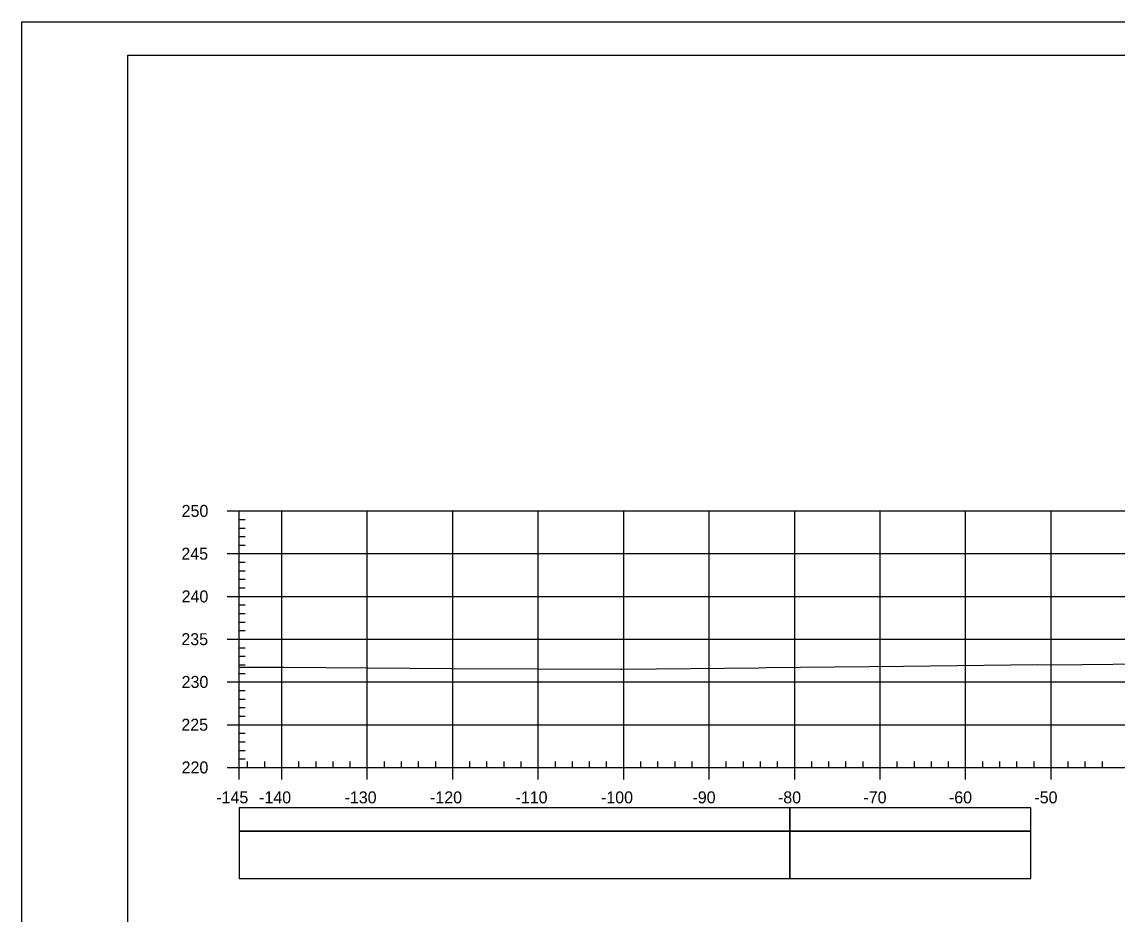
# Model space of a CAD drawing. Extents: x 1386544 to 1388153, y 379785 to 390999.
# Drawn here: x 1387819.8 to 1387948, y 384146.7 to 384251 of the extents above; entities that cross this region are included whole.
import ezdxf

# ---------------------------------------------------------------- set-up
doc = ezdxf.new("R2010")
doc.units = 0
for name, color, linetype in [('R_Axis', 7, 'Continuous'), ('R_Axis Annot', 7, 'Continuous'), ('R_Border', 7, 'Continuous'), ('R_Exist Surface', 7, 'Continuous'), ('R_Grid', 7, 'Continuous'), ('R_No Plot', 7, 'Continuous'), ('R_Striping', 7, 'Continuous')]:
    doc.layers.add(name, color=color, linetype=linetype)

msp = doc.modelspace()

# ---------------------------------------------------------------- linework, layer by layer
at = {"layer": 'R_Axis'}
for p, q in [((1387843.85, 384193.84), (1387845.25, 384193.84)), ((1387845.25, 384163.84), (1387845.25, 384193.84)), ((1387845.25, 384192.84), (1387845.95, 384192.84)), ((1387845.25, 384191.84), (1387845.95, 384191.84)), ((1387845.25, 384190.84), (1387845.95, 384190.84)), ((1387845.25, 384189.84), (1387845.95, 384189.84)), ((1387843.85, 384188.84), (1387845.25, 384188.84)), ((1387845.25, 384187.84), (1387845.95, 384187.84)), ((1387845.25, 384186.84), (1387845.95, 384186.84)), ((1387845.25, 384185.84), (1387845.95, 384185.84)), ((1387845.25, 384184.84), (1387845.95, 384184.84)), ((1387843.85, 384183.84), (1387845.25, 384183.84)), ((1387845.25, 384182.84), (1387845.95, 384182.84)), ((1387845.25, 384181.84), (1387845.95, 384181.84)), ((1387845.25, 384180.84), (1387845.95, 384180.84)), ((1387845.25, 384179.84), (1387845.95, 384179.84)), ((1387843.85, 384178.84), (1387845.25, 384178.84)), ((1387845.25, 384177.84), (1387845.95, 384177.84)), ((1387845.25, 384176.84), (1387845.95, 384176.84)), ((1387845.25, 384175.84), (1387845.95, 384175.84)), ((1387845.25, 384174.84), (1387845.95, 384174.84)), ((1387843.85, 384173.84), (1387845.25, 384173.84)), ((1387845.25, 384172.84), (1387845.95, 384172.84)), ((1387845.25, 384171.84), (1387845.95, 384171.84)), ((1387845.25, 384170.84), (1387845.95, 384170.84)), ((1387845.25, 384169.84), (1387845.95, 384169.84)), ((1387843.85, 384168.84), (1387845.25, 384168.84)), ((1387845.25, 384167.84), (1387845.95, 384167.84)), ((1387845.25, 384166.84), (1387845.95, 384166.84)), ((1387845.25, 384165.84), (1387845.95, 384165.84)), ((1387843.85, 384163.84), (1387845.25, 384163.84)), ((1387845.25, 384164.84), (1387845.95, 384164.84)), ((1387845.25, 384163.84), (1387845.25, 384164.54)), ((1387845.25, 384163.84), (1388135.25, 384163.84)), ((1387845.25, 384162.44), (1387845.25, 384163.84)), ((1387846.25, 384163.84), (1387846.25, 384164.54)), ((1387848.25, 384163.84), (1387848.25, 384164.54)), ((1387850.25, 384162.44), (1387850.25, 384163.84)), ((1387852.25, 384163.84), (1387852.25, 384164.54)), ((1387854.25, 384163.84), (1387854.25, 384164.54)), ((1387856.25, 384163.84), (1387856.25, 384164.54)), ((1387858.25, 384163.84), (1387858.25, 384164.54)), ((1387860.25, 384162.44), (1387860.25, 384163.84)), ((1387862.25, 384163.84), (1387862.25, 384164.54)), ((1387864.25, 384163.84), (1387864.25, 384164.54)), ((1387866.25, 384163.84), (1387866.25, 384164.54)), ((1387868.25, 384163.84), (1387868.25, 384164.54)), ((1387870.25, 384162.44), (1387870.25, 384163.84)), ((1387872.25, 384163.84), (1387872.25, 384164.54)), ((1387874.25, 384163.84), (1387874.25, 384164.54)), ((1387876.25, 384163.84), (1387876.25, 384164.54)), ((1387878.25, 384163.84), (1387878.25, 384164.54)), ((1387880.25, 384162.44), (1387880.25, 384163.84)), ((1387882.25, 384163.84), (1387882.25, 384164.54)), ((1387884.25, 384163.84), (1387884.25, 384164.54)), ((1387886.25, 384163.84), (1387886.25, 384164.54)), ((1387888.25, 384163.84), (1387888.25, 384164.54)), ((1387890.25, 384162.44), (1387890.25, 384163.84)), ((1387892.25, 384163.84), (1387892.25, 384164.54)), ((1387894.25, 384163.84), (1387894.25, 384164.54)), ((1387896.25, 384163.84), (1387896.25, 384164.54)), ((1387898.25, 384163.84), (1387898.25, 384164.54)), ((1387900.25, 384162.44), (1387900.25, 384163.84)), ((1387902.25, 384163.84), (1387902.25, 384164.54)), ((1387904.25, 384163.84), (1387904.25, 384164.54)), ((1387906.25, 384163.84), (1387906.25, 384164.54)), ((1387908.25, 384163.84), (1387908.25, 384164.54)), ((1387910.25, 384162.44), (1387910.25, 384163.84)), ((1387912.25, 384163.84), (1387912.25, 384164.54)), ((1387914.25, 384163.84), (1387914.25, 384164.54)), ((1387916.25, 384163.84), (1387916.25, 384164.54)), ((1387918.25, 384163.84), (1387918.25, 384164.54)), ((1387920.25, 384162.44), (1387920.25, 384163.84)), ((1387922.25, 384163.84), (1387922.25, 384164.54)), ((1387924.25, 384163.84), (1387924.25, 384164.54)), ((1387926.25, 384163.84), (1387926.25, 384164.54)), ((1387928.25, 384163.84), (1387928.25, 384164.54)), ((1387930.25, 384162.44), (1387930.25, 384163.84)), ((1387932.25, 384163.84), (1387932.25, 384164.54)), ((1387934.25, 384163.84), (1387934.25, 384164.54)), ((1387936.25, 384163.84), (1387936.25, 384164.54)), ((1387938.25, 384163.84), (1387938.25, 384164.54)), ((1387940.25, 384162.44), (1387940.25, 384163.84)), ((1387942.25, 384163.84), (1387942.25, 384164.54)), ((1387944.25, 384163.84), (1387944.25, 384164.54)), ((1387946.25, 384163.84), (1387946.25, 384164.54))]:
    msp.add_line(p, q, dxfattribs=at)
at = {"layer": 'R_Axis Annot'}
for points in [[(1387845.25, 384156.39), (1387909.69, 384156.39), (1387909.69, 384159.1), (1387845.25, 384159.1)], [(1387845.25, 384150.87), (1387909.69, 384150.87), (1387909.69, 384156.39), (1387845.25, 384156.39)]]:
    msp.add_lwpolyline(points, close=True, dxfattribs=at)
at = {"layer": 'R_Border'}
for p, q in [((1387832.25, 384247.13), (1388148.43, 384247.13)), ((1387832.25, 384041.67), (1387832.25, 384247.13))]:
    msp.add_line(p, q, dxfattribs=at)
at = {"layer": 'R_Exist Surface'}
msp.add_lwpolyline([(1387845.25, 384175.58), (1387850.51, 384175.55), (1387870.11, 384175.43), (1387870.28, 384175.43), (1387889.91, 384175.32), (1387890.04, 384175.32), (1387906.04, 384175.49), (1387906.93, 384175.52), (1387922.99, 384175.7), (1387938.64, 384175.88), (1387940.16, 384175.85), (1387954.81, 384176)], dxfattribs=at)
at = {"layer": 'R_Grid'}
for p, q in [((1387845.25, 384193.84), (1388135.25, 384193.84)), ((1387845.25, 384163.84), (1387845.25, 384193.84)), ((1387850.25, 384163.84), (1387850.25, 384193.84)), ((1387860.25, 384163.84), (1387860.25, 384193.84)), ((1387870.25, 384163.84), (1387870.25, 384193.84)), ((1387880.25, 384163.84), (1387880.25, 384193.84)), ((1387890.25, 384163.84), (1387890.25, 384193.84)), ((1387900.25, 384163.84), (1387900.25, 384193.84)), ((1387910.25, 384163.84), (1387910.25, 384193.84)), ((1387920.25, 384163.84), (1387920.25, 384193.84)), ((1387930.25, 384163.84), (1387930.25, 384193.84)), ((1387940.25, 384163.84), (1387940.25, 384193.84)), ((1387845.25, 384188.84), (1388135.25, 384188.84)), ((1387845.25, 384183.84), (1388135.25, 384183.84)), ((1387845.25, 384178.84), (1388135.25, 384178.84)), ((1387845.25, 384173.84), (1388135.25, 384173.84)), ((1387845.25, 384168.84), (1388135.25, 384168.84)), ((1387845.25, 384163.84), (1388135.25, 384163.84))]:
    msp.add_line(p, q, dxfattribs=at)
at = {"layer": 'R_No Plot'}
msp.add_line((1387819.85, 384251.02), (1388153.18, 384251.02), dxfattribs=at)
for points in [[(1387819.84, 384251.02), (1388153.18, 384251.02), (1388153.18, 384037.69), (1387819.84, 384037.69)], [(1388066.17, 384247.13), (1388085.79, 384247.13), (1388085.79, 384237.25), (1388101.9, 384237.25), (1388125.1, 384237.25), (1388125.1, 384212.92), (1388148.43, 384212.92), (1388148.43, 384041.67), (1387832.25, 384041.67), (1387832.25, 384247.13)]]:
    msp.add_lwpolyline(points, close=True, dxfattribs=at)
at = {"layer": 'R_Striping'}
for points in [[(1387909.69, 384156.4), (1387937.87, 384156.4), (1387937.87, 384159.1), (1387909.69, 384159.1)], [(1387909.69, 384150.87), (1387937.87, 384150.87), (1387937.87, 384156.4), (1387909.69, 384156.4)]]:
    msp.add_lwpolyline(points, close=True, dxfattribs=at)

# ---------------------------------------------------------------- texts
at = {"layer": 'R_Axis Annot'}
for s, p in [('250', (1387838.53, 384193.14)), ('245', (1387838.5, 384188.14)), ('240', (1387838.53, 384183.14)), ('235', (1387838.5, 384178.14)), ('230', (1387838.53, 384173.14)), ('225', (1387838.5, 384168.14)), ('220', (1387838.53, 384163.14)), ('-145', (1387842.58, 384159.64)), ('-140', (1387847.59, 384159.64)), ('-130', (1387857.59, 384159.64)), ('-120', (1387867.59, 384159.64)), ('-110', (1387877.59, 384159.64)), ('-100', (1387887.59, 384159.64)), ('-90', (1387898.29, 384159.64)), ('-80', (1387908.29, 384159.64)), ('-70', (1387918.29, 384159.64)), ('-60', (1387928.29, 384159.64)), ('-50', (1387938.29, 384159.64))]:
    msp.add_text(s, height=1.4, dxfattribs=at).set_placement(p)

doc.saveas('drawing.dxf')
